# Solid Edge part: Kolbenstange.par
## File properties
Username: ahadarics
Dokumentum tartalom típus: 0
Author: ahadarics
Last saved by: ahadarics
Revision: 85
Sűrűség: 0,000 kg/m^3
Pontosság: 0,990
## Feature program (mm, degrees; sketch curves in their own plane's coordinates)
base feature "unnamed BaseFeature 1"
thread "unnamed Thread 1"
chamfer "Letörés_1" setback 0.5
sketch for "Kihúzás_1" plane through (37.5, 0, 0) normal (1, 0, 0) x-axis (0, 0, 1)
  circle centre (0, 0) radius 8
extrude "Kihúzás_1" add finite 16 along -normal
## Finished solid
Body 1: solid body, 13 faces, 23 edges, 12 vertices.
  Faces by surface: plane 9, cylinder 3, cone 1
  Edges by curve: line 12, circle 11
Bounding box of the edges (mm): 314.500 x 16.000 x 16.000, from (-277, -8, -8) to (37.5, 8, 8).
Cylindrical faces by radius (mm): R3 x2, R8 x1
Conical faces (half-angle, radius in mm at the cone's reference point): 45 deg R2.5 x1
Planar faces by outward normal: +x 3, +z 1, -x 4, -z 1
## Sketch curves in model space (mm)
circle centre (37.5, 0, 0) radius 8
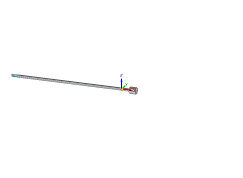
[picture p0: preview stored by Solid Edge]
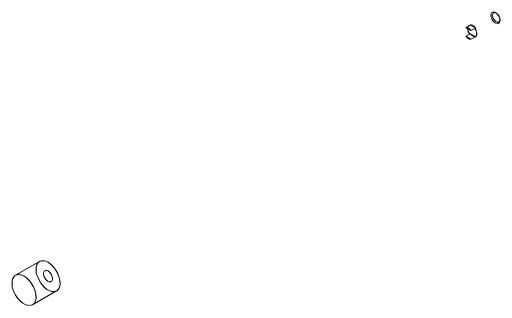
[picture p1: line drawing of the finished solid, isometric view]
